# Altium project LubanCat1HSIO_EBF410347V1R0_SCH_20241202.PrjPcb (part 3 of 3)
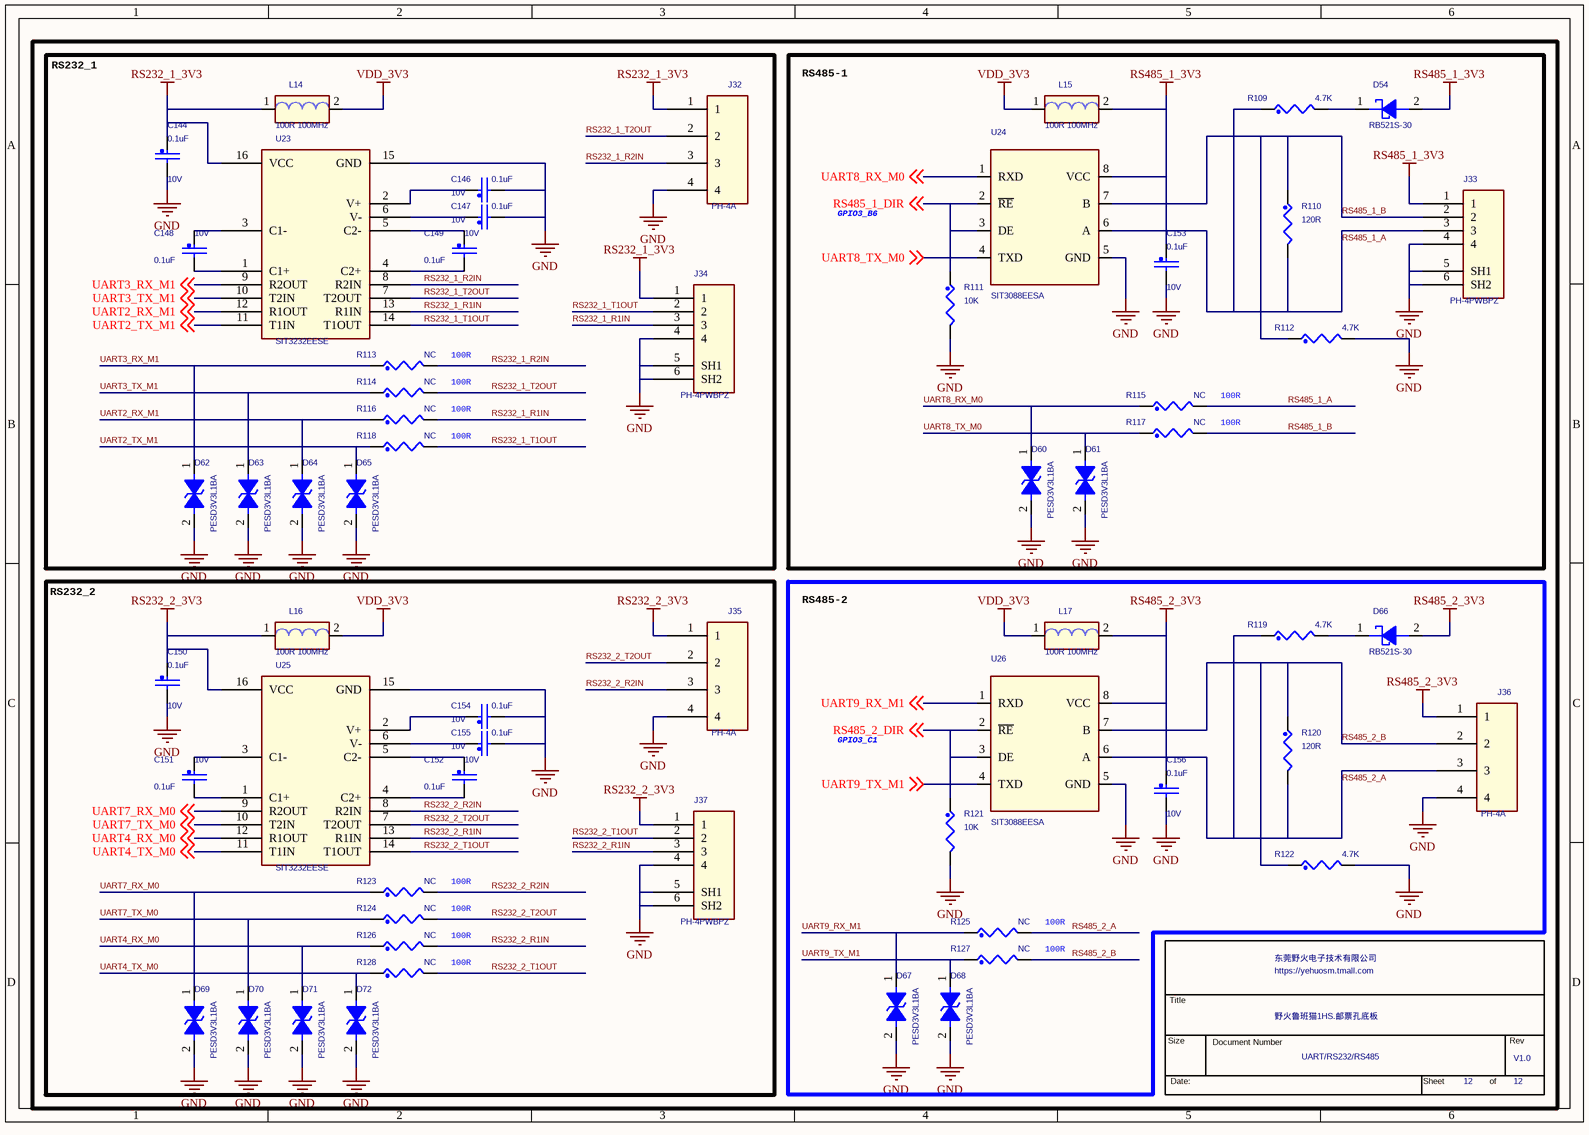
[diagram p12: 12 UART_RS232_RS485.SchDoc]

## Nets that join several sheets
12V: 03 电源 (17 pins), 05 RJ45网口_RTC_FAN (R133.1), 06 音频_SD卡 (R19.1 R30.1), 09 MIPI DSI_LVDS接口 (R79.1)
GND: 03 电源 (41 pins), 04 邮票孔连接器 (44 pins), 05 RJ45网口_RTC_FAN (31 pins), 06 音频_SD卡 (49 pins), 07 USB3 (84 pins), 08 LED_IR_GPIO引出_MASKRO (33 pins), 09 MIPI DSI_LVDS接口 (79 pins), 10 MIPI CSI接口 (28 pins), 11 WIFI_蓝牙 (20 pins), 12 UART_RS232_RS485 (40 pins)
VCC3V3_SD: 04 邮票孔连接器 (J3.8), 06 音频_SD卡 (C52.1 C53.1 D8.1 J7.4)
VCC5V0_SYS: 03 电源 (6 pins), 04 邮票孔连接器 (J3.1 J3.2)
VCC5V0_USB: 03 电源 (5 pins), 07 USB3 (U7.5 U9.5)
VCCA_1V8: 04 邮票孔连接器 (J3.7 R171.1), 07 USB3 (J26.1 J27.1)
VCCIO_ACODEC: 04 邮票孔连接器 (J3.9), 06 音频_SD卡 (R18.2)
VDD_3V3: 03 电源 (8 pins), 04 邮票孔连接器 (6 pins), 05 RJ45网口_RTC_FAN (D43.2), 06 音频_SD卡 (R31.2), 07 USB3 (6 pins), 08 LED_IR_GPIO引出_MASKRO (11 pins), 09 MIPI DSI_LVDS接口 (18 pins), 11 WIFI_蓝牙 (R167.1), 12 UART_RS232_RS485 (L14.2 L15.1 L16.2 L17.1)
VDD_5V: 03 电源 (5 pins), 05 RJ45网口_RTC_FAN (R132.1), 06 音频_SD卡 (R21.1 R32.1), 08 LED_IR_GPIO引出_MASKRO (5 pins), 09 MIPI DSI_LVDS接口 (6 pins), 10 MIPI CSI接口 (R168.1 R169.1 R170.1 R172.1)
BT_HOST_WAKE: 04 邮票孔连接器 (J3.46), 11 WIFI_蓝牙 (R158.1)
BT_REG_ON: 04 邮票孔连接器 (J3.47), 11 WIFI_蓝牙 (R155.2)
BT_WAKE: 04 邮票孔连接器 (J3.45), 11 WIFI_蓝牙 (R156.1)
CAM0_nRST: 08 LED_IR_GPIO引出_MASKRO (U17.5), 10 MIPI CSI接口 (J24.22)
CAM0_PWDN: 08 LED_IR_GPIO引出_MASKRO (U17.4), 10 MIPI CSI接口 (J24.15)
CAM1_nRST: 08 LED_IR_GPIO引出_MASKRO (U17.7), 10 MIPI CSI接口 (J28.22)
CAM1_PWDN: 08 LED_IR_GPIO引出_MASKRO (U17.6), 10 MIPI CSI接口 (J28.15)
CAM2_nRST: 08 LED_IR_GPIO引出_MASKRO (U17.9), 10 MIPI CSI接口 (J29.22)
CAM2_PWDN: 08 LED_IR_GPIO引出_MASKRO (U17.8), 10 MIPI CSI接口 (J29.15)
CAM3_nRST: 08 LED_IR_GPIO引出_MASKRO (U17.11), 10 MIPI CSI接口 (J30.22)
CAM3_PWDN: 08 LED_IR_GPIO引出_MASKRO (U17.10), 10 MIPI CSI接口 (J30.15)
CLK_32K_IN: 04 邮票孔连接器 (J3.200), 05 RJ45网口_RTC_FAN (R135.2)
ETH_PHY_LED1: 04 邮票孔连接器 (J3.164), 05 RJ45网口_RTC_FAN (J10.10)
ETH_PHY_LED2: 04 邮票孔连接器 (J3.165), 05 RJ45网口_RTC_FAN (J10.12)
ETH_PHY_MDIN0: 04 邮票孔连接器 (J3.153), 05 RJ45网口_RTC_FAN (C55.1)
ETH_PHY_MDIN1: 04 邮票孔连接器 (J3.156), 05 RJ45网口_RTC_FAN (C57.1)
ETH_PHY_MDIN2: 04 邮票孔连接器 (J3.159), 05 RJ45网口_RTC_FAN (C59.1)
ETH_PHY_MDIN3: 04 邮票孔连接器 (J3.162), 05 RJ45网口_RTC_FAN (C61.1)
ETH_PHY_MDIP0: 04 邮票孔连接器 (J3.152), 05 RJ45网口_RTC_FAN (C54.1)
ETH_PHY_MDIP1: 04 邮票孔连接器 (J3.155), 05 RJ45网口_RTC_FAN (C56.1)
ETH_PHY_MDIP2: 04 邮票孔连接器 (J3.158), 05 RJ45网口_RTC_FAN (C58.1)
ETH_PHY_MDIP3: 04 邮票孔连接器 (J3.161), 05 RJ45网口_RTC_FAN (C60.1)
EXT_PWR_EN: 03 电源 (R3.2), 04 邮票孔连接器 (J3.13)
FAN_CTRL: 04 邮票孔连接器 (J3.40), 05 RJ45网口_RTC_FAN (R137.1)
GPIO0_C0: 04 邮票孔连接器 (J3.38), 08 LED_IR_GPIO引出_MASKRO (R248.1 R253.1)
GPIO0_C1: 04 邮票孔连接器 (J3.39), 08 LED_IR_GPIO引出_MASKRO (R255.1 R257.1)
GPIO0_C6: 04 邮票孔连接器 (J3.43), 08 LED_IR_GPIO引出_MASKRO (R241.1 R242.1)
GPIO0_C7: 04 邮票孔连接器 (J3.44), 08 LED_IR_GPIO引出_MASKRO (R243.1 R244.1)
HP_BUTTON_DET: 04 邮票孔连接器 (J3.33), 06 音频_SD卡 (C40.1 R26.2 R29.1)
HP_PLUG_IN_DET: 04 邮票孔连接器 (J3.196), 06 音频_SD卡 (R36.2)
HP_SNS: 04 邮票孔连接器 (J3.22), 06 音频_SD卡 (R38.2)
HPL_OUT: 04 邮票孔连接器 (J3.21), 06 音频_SD卡 (C34.1 R33.2)
HPR_OUT: 04 邮票孔连接器 (J3.23), 06 音频_SD卡 (C46.1 R34.2)
I2C0_SCL: 04 邮票孔连接器 (J3.194), 05 RJ45网口_RTC_FAN (U15.6), 08 LED_IR_GPIO引出_MASKRO (U17.22), 10 MIPI CSI接口 (J24.6)
I2C0_SDA: 04 邮票孔连接器 (J3.193), 05 RJ45网口_RTC_FAN (U15.5), 08 LED_IR_GPIO引出_MASKRO (U17.23), 10 MIPI CSI接口 (J24.5)
I2C1_SCL_M1: 04 邮票孔连接器 (J3.57 R174.2), 09 MIPI DSI_LVDS接口 (J18.9 J19.4 R74.1), 10 MIPI CSI接口 (J28.6)
I2C1_SDA_M1: 04 邮票孔连接器 (J3.58 R175.2), 09 MIPI DSI_LVDS接口 (J18.10 J19.5 R75.1), 10 MIPI CSI接口 (J28.5)
I2C2_SCL_M1: 04 邮票孔连接器 (J3.55 R189.2), 10 MIPI CSI接口 (J29.6)
I2C2_SDA_M1: 04 邮票孔连接器 (J3.56 R190.2), 10 MIPI CSI接口 (J29.5)
I2C5_SCL_M1: 04 邮票孔连接器 (J3.148 R191.2), 10 MIPI CSI接口 (J30.6)
I2C5_SDA_M1: 04 邮票孔连接器 (J3.149 R192.2), 10 MIPI CSI接口 (J30.5)
I2S2_LRCK_M0: 04 邮票孔连接器 (J3.182), 11 WIFI_蓝牙 (R157.2)
I2S2_SCLK_M0: 04 邮票孔连接器 (J3.184), 11 WIFI_蓝牙 (R160.2)
I2S2_SDI_M0: 04 邮票孔连接器 (J3.185), 11 WIFI_蓝牙 (R161.2)
I2S2_SDO_M0: 04 邮票孔连接器 (J3.186), 11 WIFI_蓝牙 (R159.2)
LCD_BL_PWM: 04 邮票孔连接器 (J3.64), 09 MIPI DSI_LVDS接口 (R184.1 R185.1)
LCD_CPT_INT: 04 邮票孔连接器 (J3.60), 09 MIPI DSI_LVDS接口 (R81.1 R178.1)
LCD_CPT_RST: 04 邮票孔连接器 (J3.59), 09 MIPI DSI_LVDS接口 (R182.1 R183.1)
LCD_RST: 04 邮票孔连接器 (J3.63), 09 MIPI DSI_LVDS接口 (R186.1 R187.1)
LED_BLUE: 04 邮票孔连接器 (J3.183), 08 LED_IR_GPIO引出_MASKRO (R103.1)
LVDS_BL_EN: 04 邮票孔连接器 (J3.54), 09 MIPI DSI_LVDS接口 (R213.1 U21.3)
MIC1_INN: 04 邮票孔连接器 (J3.19), 06 音频_SD卡 (J4.1 R27.2)
MIC1_INP: 04 邮票孔连接器 (J3.18), 06 音频_SD卡 (J4.2 R23.2)
MIPI_CSI_RX0_CLK0N: 04 邮票孔连接器 (J3.132), 10 MIPI CSI接口 (J24.10)
MIPI_CSI_RX0_CLK0P: 04 邮票孔连接器 (J3.131), 10 MIPI CSI接口 (J24.9)
MIPI_CSI_RX0_CLK1N: 04 邮票孔连接器 (J3.124), 10 MIPI CSI接口 (J28.10)
MIPI_CSI_RX0_CLK1P: 04 邮票孔连接器 (J3.123), 10 MIPI CSI接口 (J28.9)
MIPI_CSI_RX0_D0N: 04 邮票孔连接器 (J3.129), 10 MIPI CSI接口 (J24.12)
MIPI_CSI_RX0_D0P: 04 邮票孔连接器 (J3.128), 10 MIPI CSI接口 (J24.11)
MIPI_CSI_RX0_D1N: 04 邮票孔连接器 (J3.127), 10 MIPI CSI接口 (J24.8)
MIPI_CSI_RX0_D1P: 04 邮票孔连接器 (J3.126), 10 MIPI CSI接口 (J24.7)
MIPI_CSI_RX0_D2N: 04 邮票孔连接器 (J3.121), 10 MIPI CSI接口 (J28.12)
MIPI_CSI_RX0_D2P: 04 邮票孔连接器 (J3.120), 10 MIPI CSI接口 (J28.11)
MIPI_CSI_RX0_D3N: 04 邮票孔连接器 (J3.119), 10 MIPI CSI接口 (J28.8)
MIPI_CSI_RX0_D3P: 04 邮票孔连接器 (J3.118), 10 MIPI CSI接口 (J28.7)
MIPI_CSI_RX1_CLK0N: 04 邮票孔连接器 (J3.116), 10 MIPI CSI接口 (J29.10)
MIPI_CSI_RX1_CLK0P: 04 邮票孔连接器 (J3.115), 10 MIPI CSI接口 (J29.9)
MIPI_CSI_RX1_CLK1N: 04 邮票孔连接器 (J3.108), 10 MIPI CSI接口 (J30.10)
MIPI_CSI_RX1_CLK1P: 04 邮票孔连接器 (J3.107), 10 MIPI CSI接口 (J30.9)
MIPI_CSI_RX1_D0N: 04 邮票孔连接器 (J3.113), 10 MIPI CSI接口 (J29.12)
MIPI_CSI_RX1_D0P: 04 邮票孔连接器 (J3.112), 10 MIPI CSI接口 (J29.11)
MIPI_CSI_RX1_D1N: 04 邮票孔连接器 (J3.111), 10 MIPI CSI接口 (J29.8)
MIPI_CSI_RX1_D1P: 04 邮票孔连接器 (J3.110), 10 MIPI CSI接口 (J29.7)
MIPI_CSI_RX1_D2N: 04 邮票孔连接器 (J3.105), 10 MIPI CSI接口 (J30.12)
MIPI_CSI_RX1_D2P: 04 邮票孔连接器 (J3.104), 10 MIPI CSI接口 (J30.11)
MIPI_CSI_RX1_D3N: 04 邮票孔连接器 (J3.103), 10 MIPI CSI接口 (J30.8)
MIPI_CSI_RX1_D3P: 04 邮票孔连接器 (J3.102), 10 MIPI CSI接口 (J30.7)
MIPI_DSI_TX_CLKN: 04 邮票孔连接器 (J3.135), 09 MIPI DSI_LVDS接口 (R106.1 R107.1)
MIPI_DSI_TX_CLKP: 04 邮票孔连接器 (J3.134), 09 MIPI DSI_LVDS接口 (R104.1 R105.1)
MIPI_DSI_TX_D0N: 04 邮票孔连接器 (J3.138), 09 MIPI DSI_LVDS接口 (R88.1 R89.1)
MIPI_DSI_TX_D0P: 04 邮票孔连接器 (J3.137), 09 MIPI DSI_LVDS接口 (R86.1 R87.1)
MIPI_DSI_TX_D1N: 04 邮票孔连接器 (J3.140), 09 MIPI DSI_LVDS接口 (R92.1 R93.1)
MIPI_DSI_TX_D1P: 04 邮票孔连接器 (J3.139), 09 MIPI DSI_LVDS接口 (R90.1 R91.1)
MIPI_DSI_TX_D2N: 04 邮票孔连接器 (J3.142), 09 MIPI DSI_LVDS接口 (R96.1 R97.1)
MIPI_DSI_TX_D2P: 04 邮票孔连接器 (J3.141), 09 MIPI DSI_LVDS接口 (R94.1 R95.1)
MIPI_DSI_TX_D3N: 04 邮票孔连接器 (J3.144), 09 MIPI DSI_LVDS接口 (R101.1 R102.1)
MIPI_DSI_TX_D3P: 04 邮票孔连接器 (J3.143), 09 MIPI DSI_LVDS接口 (R99.1 R100.1)
MIPI_LCD_PWR_EN: 04 邮票孔连接器 (J3.25), 09 MIPI DSI_LVDS接口 (R179.1)
ON/OFF_KEY: 04 邮票孔连接器 (J3.11), 05 RJ45网口_RTC_FAN (D46.2), 07 USB3 (R71.2)
PWM3_IR: 04 邮票孔连接器 (J3.199), 08 LED_IR_GPIO引出_MASKRO (R108.1)
RECOVERY/ADC_KEY: 04 邮票孔连接器 (J3.35), 07 USB3 (D34.1 J16.3)
RESET_KEY: 04 邮票孔连接器 (J3.12), 07 USB3 (R72.2)
RS485_1_DIR: 04 邮票孔连接器 (J3.62), 12 UART_RS232_RS485 (R111.1 U24.2 U24.3)
RS485_2_DIR: 04 邮票孔连接器 (J3.61), 12 UART_RS232_RS485 (R121.1 U26.2 U26.3)
RTC_INT: 04 邮票孔连接器 (J3.197), 05 RJ45网口_RTC_FAN (D45.2)
SARADC0_BOOT: 04 邮票孔连接器 (J3.36), 08 LED_IR_GPIO引出_MASKRO (R261.1)
SARADC0_IN5: 04 邮票孔连接器 (J3.32), 07 USB3 (R145.2)
SARADC0_IN6: 04 邮票孔连接器 (J3.31), 07 USB3 (R146.2)
SARADC0_IN7: 04 邮票孔连接器 (J3.30), 07 USB3 (R147.2)
SARADC1_IN0: 04 邮票孔连接器 (J3.83), 07 USB3 (R139.2)
SARADC1_IN1: 04 邮票孔连接器 (J3.82), 07 USB3 (R140.2)
SARADC1_IN2: 04 邮票孔连接器 (J3.81), 07 USB3 (R141.2)
SARADC1_IN3: 04 邮票孔连接器 (J3.80), 07 USB3 (R142.2)
SARADC1_IN4: 04 邮票孔连接器 (J3.79), 07 USB3 (R143.2)
SARADC1_IN5: 04 邮票孔连接器 (J3.78), 07 USB3 (R144.2)
SARADC1_IN6: 04 邮票孔连接器 (J3.77), 07 USB3 (R148.2)
SARADC1_IN7: 04 邮票孔连接器 (J3.76), 07 USB3 (R149.2)
SDMMC0_CLK: 04 邮票孔连接器 (J3.179), 06 音频_SD卡 (R46.1)
SDMMC0_CMD: 04 邮票孔连接器 (J3.178), 06 音频_SD卡 (R45.1)
SDMMC0_D0: 04 邮票孔连接器 (J3.174), 06 音频_SD卡 (R47.1)
SDMMC0_D1: 04 邮票孔连接器 (J3.175), 06 音频_SD卡 (R48.1)
SDMMC0_D2: 04 邮票孔连接器 (J3.176), 06 音频_SD卡 (R43.1)
SDMMC0_D3: 04 邮票孔连接器 (J3.177), 06 音频_SD卡 (R44.1)
SDMMC0_DETN: 04 邮票孔连接器 (J3.180), 06 音频_SD卡 (R49.1)
SDMMC1_CLK: 04 邮票孔连接器 (J3.172), 11 WIFI_蓝牙 (U16.17)
SDMMC1_CMD: 04 邮票孔连接器 (J3.171), 11 WIFI_蓝牙 (U16.16)
SDMMC1_D0: 04 邮票孔连接器 (J3.167), 11 WIFI_蓝牙 (U16.18)
SDMMC1_D1: 04 邮票孔连接器 (J3.168), 11 WIFI_蓝牙 (U16.19)
SDMMC1_D2: 04 邮票孔连接器 (J3.169), 11 WIFI_蓝牙 (U16.14)
SDMMC1_D3: 04 邮票孔连接器 (J3.170), 11 WIFI_蓝牙 (U16.15)
SPK_CTRL: 04 邮票孔连接器 (J3.198), 06 音频_SD卡 (R25.1 R39.1)
SPKN_OUT: 04 邮票孔连接器 (J3.16), 06 音频_SD卡 (R42.1)
SPKP_OUT: 04 邮票孔连接器 (J3.15), 06 音频_SD卡 (R41.1)
SYS_LED: 03 电源 (LED2.1), 04 邮票孔连接器 (J3.28)
UART0_RX_M0_DEBUG: 04 邮票孔连接器 (J3.52), 07 USB3 (U12.4)
UART0_TX_M0_DEBUG: 04 邮票孔连接器 (J3.51), 07 USB3 (U11.2)
UART1_CTSN_M0: 04 邮票孔连接器 (J3.191), 11 WIFI_蓝牙 (R150.1)
UART1_RTSN_M0: 04 邮票孔连接器 (J3.190), 11 WIFI_蓝牙 (R154.1)
UART1_RX_M0: 04 邮票孔连接器 (J3.189), 11 WIFI_蓝牙 (R152.1)
UART1_TX_M0: 04 邮票孔连接器 (J3.188), 11 WIFI_蓝牙 (R153.1)
UART2_RX_M1: 04 邮票孔连接器 (J3.27), 12 UART_RS232_RS485 (D64.1 R116.1 U23.12)
UART2_TX_M1: 04 邮票孔连接器 (J3.26), 12 UART_RS232_RS485 (D65.1 R118.1 U23.11)
UART3_RX_M1: 04 邮票孔连接器 (J3.65), 12 UART_RS232_RS485 (D62.1 R113.1 U23.9)
UART3_TX_M1: 04 邮票孔连接器 (J3.66), 12 UART_RS232_RS485 (D63.1 R114.1 U23.10)
UART4_RX_M0: 04 邮票孔连接器 (J3.67), 12 UART_RS232_RS485 (D71.1 R126.1 U25.12)
UART4_TX_M0: 04 邮票孔连接器 (J3.68), 12 UART_RS232_RS485 (D72.1 R128.1 U25.11)
UART7_RX_M0: 04 邮票孔连接器 (J3.69), 12 UART_RS232_RS485 (D69.1 R123.1 U25.9)
UART7_TX_M0: 04 邮票孔连接器 (J3.70), 12 UART_RS232_RS485 (D70.1 R124.1 U25.10)
UART8_RX_M0: 04 邮票孔连接器 (J3.71), 12 UART_RS232_RS485 (D60.1 R115.1 U24.1)
UART8_TX_M0: 04 邮票孔连接器 (J3.72), 12 UART_RS232_RS485 (D61.1 R117.1 U24.4)
UART9_RX_M1: 04 邮票孔连接器 (J3.73), 12 UART_RS232_RS485 (D67.1 R125.1 U26.1)
UART9_TX_M1: 04 邮票孔连接器 (J3.74), 12 UART_RS232_RS485 (D68.1 R127.1 U26.4)
USB20_HOST1_DM: 04 邮票孔连接器 (J3.94), 07 USB3 (R65.2)
USB20_HOST1_DP: 04 邮票孔连接器 (J3.93), 07 USB3 (R64.2)
USB20_HUB_PWR_EN: 04 邮票孔连接器 (J3.42), 07 USB3 (R67.1)
USB30_OTG0_DM: 04 邮票孔连接器 (J3.97), 07 USB3 (R52.2)
USB30_OTG0_DP: 04 邮票孔连接器 (J3.96), 07 USB3 (R53.2)
USB30_OTG0_ID: 04 邮票孔连接器 (J3.99), 07 USB3 (R193.2)
USB30_OTG0_SSRXN: 04 邮票孔连接器 (J3.89), 07 USB3 (R54.2)
USB30_OTG0_SSRXP: 04 邮票孔连接器 (J3.88), 07 USB3 (R55.2)
USB30_OTG0_SSTXN: 04 邮票孔连接器 (J3.91), 07 USB3 (C63.2)
USB30_OTG0_SSTXP: 04 邮票孔连接器 (J3.90), 07 USB3 (C64.2)
USB30_OTG0_VBUSDET: 04 邮票孔连接器 (J3.100), 07 USB3 (R58.2 R59.1)
USB30_OTG_PWR_EN: 04 邮票孔连接器 (J3.41), 07 USB3 (R56.1)
WL_HOST_WAKE: 04 邮票孔连接器 (J3.49), 11 WIFI_蓝牙 (R166.1)
WL_REG_ON: 04 邮票孔连接器 (J3.48), 11 WIFI_蓝牙 (R165.1)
